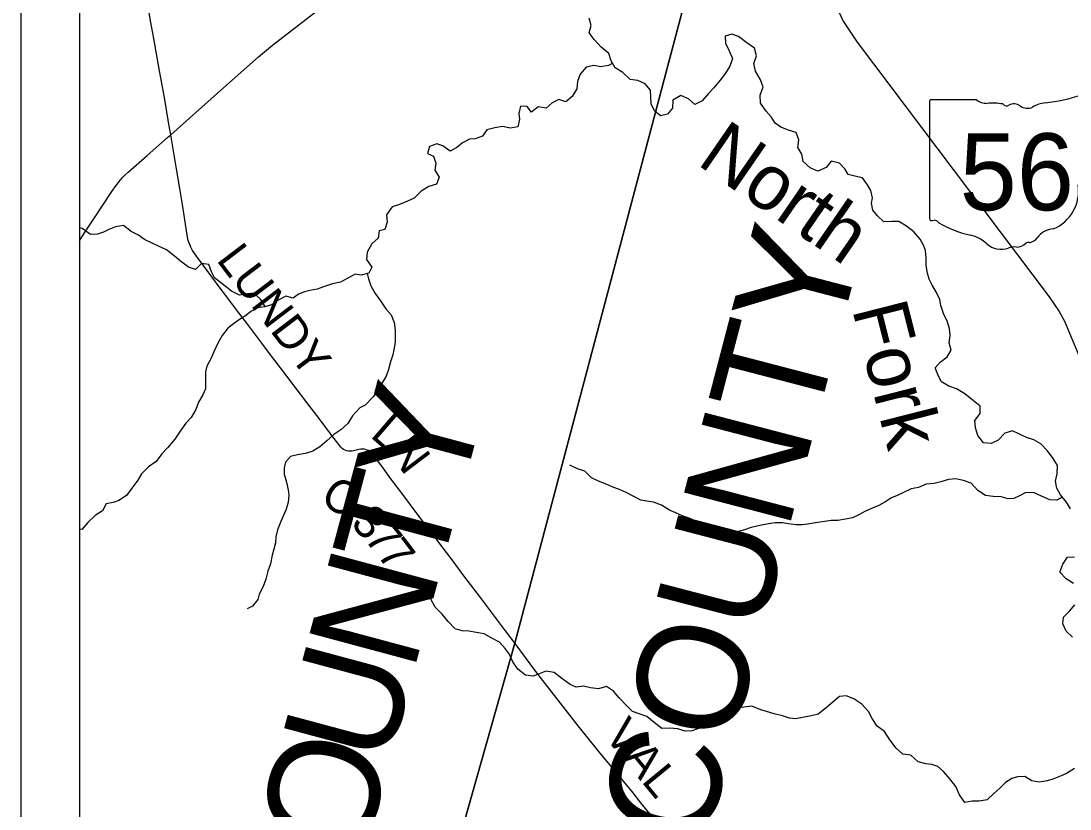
# Model space of a CAD drawing. Extents: x 0 to 36.5, y 0 to 25.3.
# Drawn here: x 2 to 3.798, y 18.753 to 20.103 of the extents above; entities that cross this region are included whole.
import ezdxf

# ---------------------------------------------------------------- set-up
doc = ezdxf.new("R2010")
doc.units = 0
for name, color, linetype in [('DV_X_Township_Line', 7, 'Continuous'), ('GM_X_County_Road', 7, 'Continuous'), ('GM_X_County_Road_Text', 7, 'Continuous'), ('GM_X_County_Text', 7, 'Continuous'), ('GM_X_Minor_River', 7, 'Continuous'), ('GM_X_Minor_River_Text', 7, 'Continuous'), ('GM_X_State_Route', 7, 'Continuous'), ('GM_X_State_Shield', 7, 'Continuous'), ('GM_X_Township_Road', 7, 'Continuous'), ('GM_X_Township_Road_Text', 7, 'Continuous'), ('SH_Cut_Line', 7, 'Continuous'), ('SH_Data', 7, 'Continuous')]:
    doc.layers.add(name, color=color, linetype=linetype)

msp = doc.modelspace()

# ---------------------------------------------------------------- linework, layer by layer
at = {"layer": 'DV_X_Township_Line'}
msp.add_lwpolyline([(3.3366, 20.9), (2.1, 20.9), (2.1, 17.5234), (2.4192, 17.4891), (2.5144, 17.8445), (2.5165, 17.8524), (2.5226, 17.8751), (2.5271, 17.8912), (2.6265, 18.2595), (2.8463, 19.037), (3.2612, 20.6041)], close=True, dxfattribs=at)
msp.add_lwpolyline([(4.5783, 20.9), (3.3366, 20.9), (3.2612, 20.6041), (2.8463, 19.037), (2.6265, 18.2595), (2.5271, 17.8912), (2.5226, 17.8751), (2.5165, 17.8524), (2.5144, 17.8445), (2.4192, 17.4891), (2.3437, 17.2326), (2.3403, 17.2198), (2.1039, 16.2931), (2.4938, 16.3413), (4.0938, 16.595), (4.8891, 16.7511), (5.1383, 16.6527), (6.6079, 15.9978)], dxfattribs=at)
at = {"layer": 'GM_X_County_Road'}
for points in [[(2.2567, 19.9077), (2.2536, 19.9257), (2.2457, 19.9716), (2.2375, 20.0174), (2.2278, 20.0725), (2.2227, 20.1), (2.217, 20.1337), (2.2117, 20.1643), (2.2085, 20.1826), (2.202, 20.2193), (2.1927, 20.2713), (2.1832, 20.3264), (2.1783, 20.3539), (2.1719, 20.3906), (2.1655, 20.4273), (2.1638, 20.4363)], [(2.2567, 19.9077), (2.3418, 19.9835), (2.4068, 20.0414), (2.4308, 20.0611), (2.5335, 20.1415)], [(2.1, 19.7262), (2.1076, 19.7382), (2.1248, 19.764), (2.1558, 19.8106), (2.1633, 19.821), (2.1667, 19.8256), (2.1708, 19.8305), (2.1747, 19.8349), (2.1788, 19.839), (2.1836, 19.8436), (2.2163, 19.8722), (2.2513, 19.9029), (2.2567, 19.9077)], [(2.8465, 19.0365), (2.8301, 19.0581), (2.8078, 19.088), (2.7872, 19.1152), (2.7591, 19.1524), (2.7403, 19.1772), (2.7236, 19.1995), (2.7067, 19.2218), (2.6804, 19.2564), (2.6525, 19.2938), (2.6338, 19.3186), (2.6209, 19.336), (2.6061, 19.3561), (2.6021, 19.361), (2.5999, 19.3632), (2.5974, 19.3653), (2.5947, 19.367), (2.5917, 19.3683), (2.5886, 19.3691), (2.5854, 19.3694), (2.5821, 19.3692), (2.579, 19.3687), (2.5699, 19.3664), (2.5669, 19.3659), (2.5639, 19.3657), (2.561, 19.3659), (2.5581, 19.3664), (2.5553, 19.3674), (2.5527, 19.3688), (2.5503, 19.3706), (2.5482, 19.3728), (2.5462, 19.3751), (2.5312, 19.3949), (2.5126, 19.4197), (2.4899, 19.4493), (2.4444, 19.5084), (2.4278, 19.5308), (2.4129, 19.5508), (2.3886, 19.583), (2.3678, 19.6101), (2.353, 19.63), (2.3398, 19.6473), (2.3285, 19.6621), (2.3137, 19.6821), (2.3009, 19.6996), (2.2939, 19.7098), (2.2909, 19.7151), (2.2885, 19.7207), (2.2867, 19.7266), (2.2855, 19.7326), (2.2824, 19.7509), (2.2771, 19.7847), (2.2726, 19.8123), (2.2672, 19.846), (2.262, 19.8767), (2.2567, 19.9077)]]:
    msp.add_lwpolyline(points, dxfattribs=at)
at = {"layer": 'GM_X_Minor_River'}
for points in [[(3.08, 19.9608), (3.0787, 19.9843), (3.0693, 19.9953), (3.0572, 20.0007), (3.0439, 20.0027), (3.0311, 20.0146), (3.0183, 20.0227), (3.0115, 20.0345), (3.0071, 20.047), (2.9939, 20.0581), (2.9822, 20.0711), (2.9736, 20.0822), (2.9771, 20.0951), (2.9738, 20.1076)], [(3.2182, 20.0802), (3.2064, 20.0766), (3.207, 20.0648), (3.2137, 20.0514), (3.2193, 20.0385), (3.2146, 20.0256), (3.2073, 20.0131), (3.1981, 20.0011), (3.1874, 19.9883), (3.1778, 19.9785), (3.1674, 19.966), (3.1549, 19.9597), (3.1436, 19.9696), (3.1307, 19.9751), (3.117, 19.9672), (3.1165, 19.9535), (3.1077, 19.943), (3.0959, 19.9404), (3.0857, 19.9489), (3.08, 19.9608)], [(3.7983, 19.2672), (3.7912, 19.2787), (3.7811, 19.2909), (3.7747, 19.3024), (3.7729, 19.3145), (3.7753, 19.327), (3.7762, 19.3411), (3.7687, 19.3533), (3.759, 19.3663), (3.7473, 19.3781), (3.7356, 19.3854), (3.7231, 19.3893), (3.7107, 19.3951), (3.699, 19.4005), (3.686, 19.3969), (3.6745, 19.3844), (3.6623, 19.3792), (3.6491, 19.3801), (3.6397, 19.3927), (3.6353, 19.4056), (3.6346, 19.4182), (3.6438, 19.4302), (3.6436, 19.4428), (3.6292, 19.4543), (3.6172, 19.4642), (3.6028, 19.4727), (3.5896, 19.4774), (3.5775, 19.4847), (3.5719, 19.4942), (3.5667, 19.5083), (3.5752, 19.5181), (3.587, 19.5275), (3.5936, 19.5388), (3.5903, 19.5514), (3.5923, 19.5639), (3.5909, 19.5761), (3.5868, 19.5886), (3.5805, 19.6016), (3.5764, 19.6153), (3.5742, 19.6256), (3.5679, 19.6389), (3.5615, 19.6503), (3.5559, 19.6606), (3.5534, 19.6705), (3.5508, 19.6838), (3.5509, 19.6971), (3.5499, 19.7093), (3.5466, 19.7188), (3.541, 19.7287), (3.5297, 19.7417), (3.5173, 19.7513), (3.5044, 19.7594), (3.4919, 19.7595), (3.4783, 19.7588), (3.4677, 19.7688), (3.4598, 19.7784), (3.4573, 19.7905), (3.4589, 19.8), (3.4563, 19.8125), (3.4504, 19.8221), (3.4417, 19.8343), (3.4289, 19.8371), (3.4171, 19.8398), (3.4115, 19.8494), (3.4025, 19.8589), (3.3885, 19.8625), (3.3797, 19.8519), (3.3652, 19.8452), (3.3523, 19.8514), (3.3403, 19.8621), (3.3381, 19.8746), (3.331, 19.8861), (3.3327, 19.8994), (3.3282, 19.9116), (3.315, 19.9155), (3.3021, 19.9209), (3.2923, 19.9278), (3.2856, 19.9385), (3.2769, 19.9484), (3.2672, 19.9622), (3.2666, 19.9758), (3.2716, 19.9898), (3.2664, 20.0032), (3.2586, 20.0165), (3.256, 20.0298), (3.2603, 20.0431), (3.2566, 20.056), (3.2438, 20.0652), (3.2295, 20.0764), (3.2182, 20.0802)], [(3.0139, 20.0303), (3.0065, 20.0262), (2.9936, 20.0244), (2.9815, 20.0264), (2.9686, 20.0238), (2.9582, 20.0117), (2.9536, 19.9992), (2.9524, 19.9863), (2.9443, 19.9731), (2.9336, 19.9645), (2.9215, 19.968), (2.9104, 19.9627), (2.8997, 19.9533), (2.8861, 19.9557), (2.875, 19.9463), (2.8671, 19.9562), (2.8561, 19.957), (2.853, 19.9445), (2.8544, 19.9343), (2.8513, 19.9214), (2.8388, 19.9192), (2.8251, 19.922), (2.8118, 19.9198), (2.7985, 19.9161), (2.7909, 19.9055), (2.7783, 19.9007), (2.7688, 19.9), (2.7566, 19.894), (2.7471, 19.8861), (2.7353, 19.8797), (2.7228, 19.8886), (2.7126, 19.892), (2.7001, 19.8876), (2.6966, 19.8755), (2.7068, 19.8712), (2.7108, 19.8594), (2.7092, 19.8473), (2.7167, 19.8351), (2.7117, 19.8233), (2.6988, 19.8193), (2.6858, 19.8114), (2.674, 19.7993), (2.6622, 19.7941), (2.6485, 19.7881), (2.6363, 19.7844), (2.6263, 19.7708), (2.6277, 19.7583), (2.6235, 19.7458), (2.6136, 19.7432), (2.612, 19.7307), (2.6009, 19.7209), (2.5932, 19.7069), (2.592, 19.694), (2.601, 19.6811), (2.596, 19.6708), (2.5827, 19.6675), (2.5728, 19.6691), (2.5602, 19.662), (2.5473, 19.6553), (2.5336, 19.6523), (2.5203, 19.6479), (2.5077, 19.6434), (2.4952, 19.6408), (2.4857, 19.6386), (2.4758, 19.6349), (2.4663, 19.6278), (2.4538, 19.6313), (2.4404, 19.6242), (2.4301, 19.6166), (2.4172, 19.6133), (2.4058, 19.6111), (2.394, 19.6048), (2.3848, 19.5977), (2.3742, 19.5913), (2.3642, 19.5841), (2.3543, 19.5766), (2.3447, 19.5641), (2.3371, 19.5509), (2.3305, 19.5361), (2.3255, 19.524), (2.3185, 19.5116), (2.3162, 19.5017), (2.3161, 19.4918), (2.3164, 19.482), (2.316, 19.4725), (2.3117, 19.4623), (2.3044, 19.4498), (2.2997, 19.4369), (2.2917, 19.4233), (2.2825, 19.4135), (2.2729, 19.4003), (2.2637, 19.3863), (2.2511, 19.3716), (2.2415, 19.361), (2.2315, 19.3482), (2.2186, 19.3392), (2.2063, 19.3268), (2.2002, 19.3162), (2.1902, 19.3026), (2.181, 19.2897), (2.1677, 19.2815)], [(2.4185, 19.6136), (2.4105, 19.6263), (2.3988, 19.6362), (2.3882, 19.6352), (2.3745, 19.633), (2.3605, 19.6399), (2.3447, 19.6522), (2.3315, 19.6625), (2.3262, 19.6728), (2.3218, 19.6854), (2.3093, 19.6874), (2.2993, 19.6768), (2.2869, 19.6811), (2.2733, 19.6911), (2.2627, 19.7002), (2.2491, 19.7106), (2.2359, 19.7168), (2.2234, 19.7225), (2.2117, 19.7283), (2.2015, 19.736), (2.1887, 19.7422), (2.1755, 19.7521), (2.1622, 19.7503), (2.1508, 19.7455), (2.1413, 19.741), (2.1314, 19.7377), (2.1192, 19.737), (2.1049, 19.747), (2.1, 19.7486)], [(2.5934, 19.6702), (2.5955, 19.661), (2.5992, 19.6492), (2.6071, 19.6358), (2.6161, 19.6232), (2.6251, 19.6099), (2.6341, 19.5996), (2.6397, 19.5863), (2.6411, 19.573), (2.6409, 19.5528), (2.6397, 19.5426), (2.6374, 19.5309), (2.6331, 19.5191), (2.63, 19.5055), (2.6257, 19.4941), (2.618, 19.4809), (2.6122, 19.4707), (2.6034, 19.4586), (2.59, 19.4447), (2.5805, 19.4398), (2.5683, 19.4262), (2.5602, 19.413), (2.548, 19.4024), (2.5358, 19.3942), (2.5239, 19.3833), (2.5121, 19.3731), (2.5003, 19.3656), (2.4877, 19.3619), (2.474, 19.3597), (2.4619, 19.3568), (2.4531, 19.347), (2.4507, 19.3371), (2.451, 19.3265), (2.4551, 19.3128), (2.458, 19.2998), (2.4591, 19.2903), (2.4578, 19.2778), (2.4539, 19.265), (2.4482, 19.2521), (2.4439, 19.2422), (2.4396, 19.2309), (2.4369, 19.2188), (2.4364, 19.2089), (2.4333, 19.1979), (2.4306, 19.1877), (2.4274, 19.1729), (2.4232, 19.16), (2.4196, 19.1468), (2.415, 19.1339), (2.4084, 19.121), (2.4057, 19.1116), (2.3969, 19.1002), (2.3874, 19.0957)], [(3.7843, 19.287), (3.7749, 19.2819), (3.7632, 19.2823), (3.7488, 19.2889), (3.7348, 19.2951), (3.7204, 19.2945), (3.7109, 19.2892), (3.701, 19.2847), (3.6915, 19.2841), (3.6794, 19.2876), (3.6661, 19.2884), (3.6528, 19.2897), (3.6396, 19.2985), (3.628, 19.3108), (3.6151, 19.3158), (3.6019, 19.3186), (3.5893, 19.3172), (3.5764, 19.3135), (3.565, 19.3106), (3.5509, 19.3095), (3.5376, 19.3036), (3.5254, 19.301), (3.5113, 19.2943), (3.5014, 19.2898), (3.4915, 19.2857), (3.4801, 19.2786), (3.4698, 19.273), (3.4576, 19.2678), (3.4458, 19.2626), (3.4355, 19.257), (3.4248, 19.2514), (3.4127, 19.2492), (3.3994, 19.247), (3.3884, 19.2471), (3.3766, 19.2453), (3.3614, 19.2428), (3.3515, 19.2413), (3.339, 19.2395), (3.328, 19.2396), (3.3151, 19.2416), (3.3049, 19.2432), (3.292, 19.243), (3.2806, 19.2412), (3.2661, 19.2386), (3.2513, 19.2353), (3.2399, 19.2313), (3.2269, 19.2276), (3.2174, 19.2265), (3.2045, 19.2259), (3.1947, 19.2256), (3.1833, 19.2291), (3.1712, 19.2364), (3.1577, 19.2452), (3.1452, 19.251), (3.1331, 19.2553), (3.1221, 19.2599), (3.1112, 19.265), (3.0976, 19.2734), (3.0836, 19.2785), (3.0722, 19.2801), (3.062, 19.2817), (3.0488, 19.2886), (3.0367, 19.2952), (3.0269, 19.2995), (3.0129, 19.3049), (3.0027, 19.3092), (2.9894, 19.3142), (2.9773, 19.32), (2.966, 19.3315), (2.9536, 19.3354), (2.9407, 19.3416)], [(2.1677, 19.2815), (2.1578, 19.2778), (2.146, 19.2756), (2.1398, 19.2635), (2.1272, 19.2556), (2.1146, 19.2435), (2.1043, 19.2318), (2.1, 19.2322)], [(3.8036, 19.1392), (3.7908, 19.1473), (3.7799, 19.1584), (3.7853, 19.172), (3.793, 19.1845), (3.8052, 19.1848)], [(2.8294, 19.0276), (2.8198, 19.0387), (2.8069, 19.0452), (2.7937, 19.0529), (2.7805, 19.0549), (2.7672, 19.0577), (2.7558, 19.0581), (2.7437, 19.0616), (2.7317, 19.0742), (2.7219, 19.0865), (2.7099, 19.0987), (2.702, 19.1124), (2.6994, 19.1219), (2.6862, 19.1315), (2.6722, 19.1388)], [(3.8017, 19.047), (3.7911, 19.0573), (3.7852, 19.0699), (3.7864, 19.0813), (3.7964, 19.0915), (3.8056, 19.1028)], [(3.805, 18.8222), (3.7916, 18.8136), (3.7821, 18.8095), (3.768, 18.8039), (3.7585, 18.8013), (3.7448, 18.7988), (3.732, 18.8008), (3.7199, 18.8085), (3.7077, 18.8082), (3.6978, 18.8053), (3.6872, 18.7981), (3.6772, 18.7883), (3.6669, 18.7793), (3.6558, 18.7688), (3.6421, 18.7662), (3.63, 18.766), (3.6174, 18.7638), (3.6081, 18.7771), (3.6021, 18.7916), (3.5916, 18.8046), (3.5807, 18.8169), (3.5709, 18.8257), (3.5607, 18.8292), (3.5505, 18.83), (3.5372, 18.8336), (3.5248, 18.845), (3.5108, 18.8467), (3.4999, 18.857), (3.489, 18.8715), (3.4796, 18.8857), (3.4668, 18.8945), (3.4586, 18.9079), (3.4522, 18.9201), (3.4406, 18.9323), (3.427, 18.9415), (3.4142, 18.9466), (3.4024, 18.9455), (3.3913, 18.9361), (3.3798, 18.926), (3.3661, 18.9151), (3.3516, 18.9118), (3.3417, 18.91), (3.3269, 18.9074), (3.3171, 18.9083), (3.3046, 18.9122), (3.2906, 18.9157), (3.2773, 18.9196), (3.2675, 18.9227), (3.2524, 18.9289), (3.2387, 18.9275), (3.2277, 18.9261), (3.2098, 18.9171), (3.1995, 18.9115), (3.1865, 18.9048), (3.1724, 18.8973), (3.1629, 18.8913), (3.1499, 18.8865), (3.1378, 18.8859), (3.1253, 18.8901), (3.1116, 18.891), (3.0983, 18.8907), (3.0852, 18.9011), (3.0724, 18.9111), (3.0591, 18.9157), (3.0481, 18.9196), (3.0376, 18.9303), (3.0252, 18.9434), (3.0154, 18.9545), (3.0034, 18.9629), (2.9893, 18.9588), (2.9757, 18.9605), (2.9639, 18.9632), (2.9514, 18.9614), (2.9412, 18.9661), (2.9269, 18.9765), (2.9137, 18.9864), (2.8993, 18.9888), (2.8878, 18.9844), (2.8779, 18.9803), (2.8647, 18.9823), (2.8511, 18.9923), (2.8429, 19.0052), (2.8365, 19.0186), (2.8294, 19.0276)]]:
    msp.add_lwpolyline(points, dxfattribs=at)
at = {"layer": 'GM_X_State_Route'}
msp.add_lwpolyline([(3.2615, 20.6035), (3.2658, 20.5889), (3.3335, 20.2794), (3.3398, 20.2554), (3.3563, 20.2152), (3.409, 20.1026), (3.4328, 20.0663), (3.762, 19.63), (3.779, 19.6053), (3.7883, 19.5885), (3.858, 19.422), (4.1004, 18.8246)], dxfattribs=at)
at = {"layer": 'GM_X_State_Shield'}
for p, q in [((3.5568, 19.9645), (3.5568, 19.7644)), ((3.6366, 19.9679), (3.5594, 19.9679))]:
    msp.add_line(p, q, dxfattribs=at)
for centre, radius, start, end in [((3.7265, 20.2408), 0.2796, 275.8445, 288.9065), ((3.5598, 19.9649), 0.00305, 98.1301, 188.1301), ((3.655, 19.9912), 0.0296, 231.6195, 271.1119), ((3.6648, 19.8556), 0.1064, 80.4867, 94.9883), ((3.689, 19.966), 0.00855, 219.7921, 297.1024), ((3.7015, 19.9428), 0.0178, 54.4667, 119.1411), ((3.7245, 19.9746), 0.0214, 233.8562, 294.8282), ((3.7622, 19.9068), 0.0563, 97.3462, 120.7689), ((3.7422, 19.8111), 0.0699, 292.3089, 8.9858), ((3.5599, 19.7639), 0.00308, 171.9584, 258.3066), ((3.5603, 19.7844), 0.0235, 267.339, 280.6039), ((3.5651, 19.7528), 0.00848, 29.7484, 93.2717), ((3.6722, 19.9326), 0.2019, 240.4129, 257.1985), ((3.7717, 19.7082), 0.0383, 94.4031, 142.5768), ((3.612, 19.6745), 0.0632, 47.1842, 75.836), ((3.6803, 19.7518), 0.0401, 230.7004, 286.2918), ((3.7064, 19.7369), 0.0214, 268.777, 315.5493), ((3.7257, 19.7175), 0.00601, 65.7517, 132.6484), ((3.7232, 19.745), 0.0226, 282.8732, 323.2771), ((3.7035, 19.6827), 0.0329, 85.6951, 111.2099)]:
    msp.add_arc(centre, radius, start, end, dxfattribs=at)
at = {"layer": 'GM_X_Township_Road'}
msp.add_lwpolyline([(3.4349, 18.304), (3.4237, 18.3202), (3.4085, 18.3397), (3.1214, 18.6905), (3.0861, 18.7343), (3.0621, 18.7634), (3.0487, 18.7805), (2.9904, 18.8512), (2.9547, 18.8951), (2.8824, 18.9881), (2.8465, 19.0365)], dxfattribs=at)
at = {"layer": 'SH_Cut_Line'}
msp.add_lwpolyline([(3.3366, 20.9), (2.1, 20.9), (2.1, 16.2788), (2.1039, 16.2931), (2.3403, 17.2198), (2.3437, 17.2326), (2.4192, 17.4891), (2.5144, 17.8445), (2.5165, 17.8524), (2.5226, 17.8751), (2.5271, 17.8912), (2.6265, 18.2595), (2.8463, 19.037), (3.2612, 20.6041)], close=True, dxfattribs=at)
msp.add_lwpolyline([(4.4591, 20.9), (3.3366, 20.9), (3.2612, 20.6041), (2.8463, 19.037), (2.6265, 18.2595), (2.5271, 17.8912), (2.5226, 17.8751), (2.5165, 17.8524), (2.5144, 17.8445), (2.4192, 17.4891), (2.3437, 17.2326), (2.3403, 17.2198), (2.1039, 16.2931), (2.1, 16.2788), (2.1, 14.1), (8.9, 14.1), (8.9, 20.9), (6.1845, 20.9)], dxfattribs=at)
at = {"layer": 'SH_Data'}
for p, q in [((2, 21), (2, 14)), ((2.1, 20.9), (2.1, 14.1))]:
    msp.add_line(p, q, dxfattribs=at)
msp.add_lwpolyline([(3.2615, 20.6035), (3.2658, 20.5889), (3.3335, 20.2794), (3.3398, 20.2554), (3.3563, 20.2152), (3.409, 20.1026), (3.4328, 20.0663), (3.762, 19.63), (3.779, 19.6053), (3.7883, 19.5885), (3.858, 19.422), (4.1004, 18.8246)], dxfattribs=at)

# ---------------------------------------------------------------- texts
at = {"layer": 'GM_X_County_Road_Text'}
for s, height, rotation, p in [('LUNDY', 0.05682, 307.2593, (2.3336, 19.6934)), ('L', 0.0568, 319.1035, (2.5967, 19.3913)), ('N', 0.0568, 307.189, (2.6266, 19.3658)), ('C', 0.0568, 325.7741, (2.5098, 19.2803)), ('-', 0.0568, 317.8602, (2.5467, 19.2554)), ('3', 0.0568, 313.3918, (2.5632, 19.2405)), ('7', 0.0568, 308.7947, (2.5865, 19.216)), ('7', 0.0568, 307.3934, (2.6082, 19.189))]:
    msp.add_text(s, height=height, rotation=rotation, dxfattribs=at).set_placement(p)
at = {"layer": 'GM_X_County_Text'}
for s, height, rotation, p in [('MADISON COUNTY', 0.189394, 75.3839, (2.8562, 17.4706)), ('Y', 0.1894, 74.9663, (2.7522, 19.2827)), ('T', 0.1894, 74.9663, (2.7155, 19.1462)), ('N', 0.1894, 74.9644, (2.6721, 18.9847)), ('U', 0.1894, 74.9655, (2.6288, 18.8233)), ('O', 0.1894, 74.9655, (2.5854, 18.6618))]:
    msp.add_text(s, height=height, rotation=rotation, dxfattribs=at).set_placement(p)
at = {"layer": 'GM_X_Minor_River_Text'}
for s, height, rotation, p in [('North', 0.09469, 325.4181, (3.1562, 19.8582)), ('Fork', 0.09468, 284.2404, (3.4238, 19.6094))]:
    msp.add_text(s, height=height, rotation=rotation, dxfattribs=at).set_placement(p)
at = {"layer": 'GM_X_State_Shield'}
msp.add_text('56', height=0.13184, dxfattribs=at).set_placement((3.6083, 19.7785))
at = {"layer": 'GM_X_Township_Road_Text'}
msp.add_text('VAL', height=0.05682, rotation=309.4245, dxfattribs=at).set_placement((2.9975, 18.8786))

doc.saveas('drawing.dxf')
